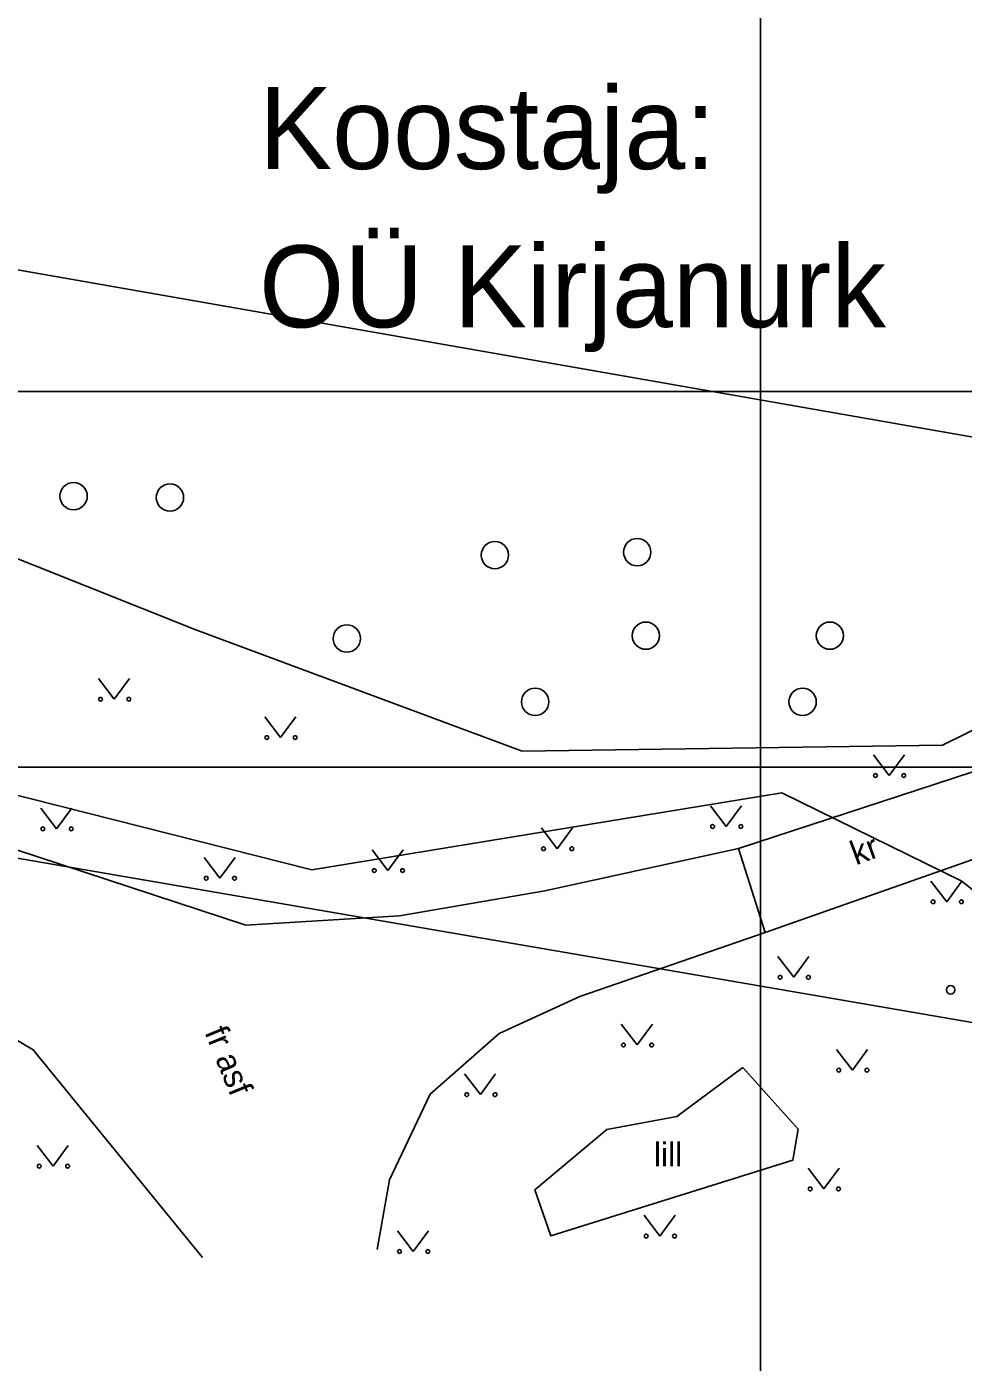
# Model space of a CAD drawing. Extents: x 554947 to 555436, y 6564938 to 6565792.
# Drawn here: x 555195.59 to 555223.03, y 6565130.48 to 6565169.6 of the extents above; entities that cross this region are included whole.
import ezdxf

# ---------------------------------------------------------------- set-up
doc = ezdxf.new("R2010")
doc.units = 0
for name, color, linetype in [('HALJASTUS', 7, 'Continuous'), ('KPOHULIIN', 7, 'Continuous'), ('PIIR', 7, 'Continuous'), ('PR_SIDE', 7, 'Continuous'), ('PUU', 7, 'Continuous'), ('TEE', 7, 'Continuous'), ('VORMISTUS', 7, 'Continuous'), ('VORMISTUS_1', 7, 'Continuous')]:
    doc.layers.add(name, color=color, linetype=linetype)

msp = doc.modelspace()

# ---------------------------------------------------------------- linework, layer by layer
at = {"layer": 'HALJASTUS'}
for p, q in [((555197.689, 6565150.508), (555198.153, 6565149.901)), ((555198.153, 6565149.901), (555198.598, 6565150.508)), ((555202.562, 6565149.385), (555203.025, 6565148.778)), ((555203.025, 6565148.778), (555203.471, 6565149.385)), ((555220.397, 6565148.274), (555220.861, 6565147.667)), ((555220.861, 6565147.667), (555221.306, 6565148.274)), ((555196, 6565146.709), (555196.464, 6565146.102)), ((555196.464, 6565146.102), (555196.909, 6565146.709)), ((555215.626, 6565146.78), (555216.089, 6565146.173)), ((555216.089, 6565146.173), (555216.535, 6565146.78)), ((555210.669, 6565146.129), (555211.133, 6565145.522)), ((555211.133, 6565145.522), (555211.578, 6565146.129)), ((555205.711, 6565145.488), (555206.174, 6565144.881)), ((555206.174, 6565144.881), (555206.62, 6565145.488)), ((555200.786, 6565145.261), (555201.25, 6565144.654)), ((555201.25, 6565144.654), (555201.695, 6565145.261)), ((555222.085, 6565144.574), (555222.548, 6565143.967)), ((555222.548, 6565143.967), (555222.994, 6565144.574)), ((555217.602, 6565142.361), (555218.065, 6565141.754)), ((555218.065, 6565141.754), (555218.511, 6565142.361)), ((555213.012, 6565140.378), (555213.475, 6565139.771)), ((555213.475, 6565139.771), (555213.921, 6565140.378)), ((555219.32, 6565139.641), (555219.783, 6565139.034)), ((555219.783, 6565139.034), (555220.229, 6565139.641)), ((555208.419, 6565138.924), (555208.883, 6565138.317)), ((555208.883, 6565138.317), (555209.328, 6565138.924)), ((555195.895, 6565136.829), (555196.358, 6565136.222)), ((555196.358, 6565136.222), (555196.804, 6565136.829)), ((555218.486, 6565136.16), (555218.949, 6565135.553)), ((555218.949, 6565135.553), (555219.395, 6565136.16)), ((555213.68, 6565134.781), (555214.143, 6565134.175)), ((555214.143, 6565134.175), (555214.589, 6565134.781)), ((555206.451, 6565134.328), (555206.914, 6565133.721)), ((555206.914, 6565133.721), (555207.36, 6565134.328))]:
    msp.add_line(p, q, dxfattribs=at)
for points in [[(555170.849, 6565163.433), (555170.802, 6565162.422), (555180.588, 6565157.338), (555194.166, 6565154.476), (555200.547, 6565151.934), (555210.105, 6565148.383), (555222.421, 6565148.556), (555228.239, 6565151.421), (555231.104, 6565153.786)], [(555216.57, 6565139.116), (555214.639, 6565137.676), (555212.583, 6565137.299), (555210.474, 6565135.526), (555210.946, 6565134.177), (555218.038, 6565136.397), (555218.195, 6565137.306), (555216.57, 6565139.116)]]:
    msp.add_lwpolyline(points, dxfattribs=at)
for centre, radius in [((555196.963, 6565155.852), 0.4), ((555199.786, 6565155.81), 0.4), ((555209.308, 6565154.124), 0.4), ((555213.479, 6565154.208), 0.4), ((555213.732, 6565151.763), 0.4), ((555219.125, 6565151.763), 0.4), ((555204.968, 6565151.678), 0.4), ((555210.488, 6565149.823), 0.4), ((555218.325, 6565149.823), 0.4), ((555197.752, 6565149.901), 0.055), ((555198.581, 6565149.901), 0.055), ((555202.624, 6565148.778), 0.055), ((555203.453, 6565148.778), 0.055), ((555220.46, 6565147.667), 0.055), ((555221.289, 6565147.667), 0.055), ((555215.688, 6565146.173), 0.055), ((555216.517, 6565146.173), 0.055), ((555196.063, 6565146.102), 0.055), ((555196.892, 6565146.102), 0.055), ((555210.732, 6565145.522), 0.055), ((555211.56, 6565145.522), 0.055), ((555200.848, 6565144.654), 0.055), ((555201.677, 6565144.654), 0.055), ((555205.773, 6565144.881), 0.055), ((555206.602, 6565144.881), 0.055), ((555222.147, 6565143.967), 0.055), ((555222.976, 6565143.967), 0.055), ((555217.664, 6565141.754), 0.055), ((555218.493, 6565141.754), 0.055), ((555213.074, 6565139.771), 0.055), ((555213.903, 6565139.771), 0.055), ((555219.382, 6565139.034), 0.055), ((555220.211, 6565139.034), 0.055), ((555208.482, 6565138.317), 0.055), ((555209.311, 6565138.317), 0.055), ((555195.957, 6565136.222), 0.055), ((555196.786, 6565136.222), 0.055), ((555218.548, 6565135.553), 0.055), ((555219.377, 6565135.553), 0.055), ((555213.742, 6565134.175), 0.055), ((555214.571, 6565134.175), 0.055), ((555206.513, 6565133.721), 0.055), ((555207.342, 6565133.721), 0.055)]:
    msp.add_circle(centre, radius, dxfattribs=at)
at = {"layer": 'KPOHULIIN'}
msp.add_lwpolyline([(555148.701, 6565153.258), (555226.644, 6565139.855), (555319.309, 6565121.586)], dxfattribs=at)
at = {"layer": 'PIIR'}
for points in [[(555293.54, 6565286.23), (555256.63, 6565245.54), (555254.61, 6565228.5), (555255.75, 6565226.79), (555261.42, 6565218.27), (555289.11, 6565186.6), (555315.28, 6565149.09), (555315.73, 6565134.86), (555310.07, 6565124.47), (555303.59, 6565115.89), (555291.54, 6565100.48), (555288.85, 6565092.31), (555275.41, 6565088.83), (555273.15, 6565087.34), (555239.11, 6565139), (555231.12, 6565150.64), (555225.89, 6565157.13), (555173.21, 6565166.35), (555173.84, 6565168.77), (555191.64, 6565237.48), (555195.28, 6565271.63)], [(555272.013, 6565013.369), (555140.74, 6565041.04), (555172.58, 6565163.93), (555173.21, 6565166.35), (555225.89, 6565157.13), (555231.12, 6565150.64), (555239.11, 6565139), (555273.15, 6565087.34), (555275.41, 6565088.83), (555288.85, 6565092.31), (555289.83, 6565088.53), (555290.166, 6565088.221)]]:
    msp.add_lwpolyline(points, dxfattribs=at)
at = {"layer": 'PR_SIDE'}
msp.add_lwpolyline([(555296.809, 6565115.615), (555286.607, 6565117.391), (555285.808, 6565118.252), (555287.837, 6565125.956), (555287.097, 6565126.919), (555245.342, 6565135.118), (555231.314, 6565137.915), (555222.994, 6565144.574), (555217.72, 6565147.16), (555203.944, 6565144.9), (555175.818, 6565152.015), (555157.882, 6565156.552), (555156.917, 6565156.236), (555156.093, 6565155.105)], dxfattribs=at)
at = {"layer": 'PUU'}
msp.add_circle((555222.663, 6565141.385), 0.125, dxfattribs=at)
at = {"layer": 'TEE'}
for points in [[(555205.86, 6565133.779), (555206.217, 6565135.824), (555207.407, 6565138.329), (555209.429, 6565140.104), (555211.794, 6565141.192), (555217.229, 6565143.067), (555216.442, 6565145.526), (555210.771, 6565144.283), (555206.511, 6565143.557), (555202.006, 6565143.277), (555191.831, 6565146.626), (555179.65, 6565150.043), (555174.155, 6565151.803), (555172.54, 6565153.141), (555170.207, 6565157.377), (555168.463, 6565160.669), (555168.3, 6565162.209)], [(555216.442, 6565145.526), (555223.819, 6565147.942), (555228.422, 6565150.319), (555233.413, 6565153.879)], [(555217.229, 6565143.067), (555224.725, 6565145.706), (555229.126, 6565147.942), (555234.467, 6565152.147)], [(555163.2, 6565141.618), (555168.594, 6565144.246), (555172.571, 6565146.598), (555178.227, 6565145.611), (555191.847, 6565141.953), (555195.778, 6565139.63), (555200.739, 6565133.541)]]:
    msp.add_lwpolyline(points, dxfattribs=at)
at = {"layer": 'VORMISTUS'}
msp.add_lwpolyline([(555217.086, 6564974.913), (555052.086, 6564974.913), (555052.086, 6565184.913), (555217.086, 6565184.913)], close=True, dxfattribs=at)
at = {"layer": 'VORMISTUS_1'}
for points in [[(555035.188, 6565444.913), (555245.188, 6565444.913), (555245.188, 6565147.913), (555035.188, 6565147.913)], [(555045.188, 6565158.913), (555235.188, 6565158.913), (555235.188, 6565433.913), (555045.188, 6565433.913)], [(555045.188, 6565433.913), (555235.188, 6565433.913), (555235.188, 6565158.913), (555045.188, 6565158.913)]]:
    msp.add_lwpolyline(points, close=True, dxfattribs=at)

# ---------------------------------------------------------------- texts
at = {"layer": 'HALJASTUS'}
msp.add_text('lill', height=0.7, dxfattribs=at).set_placement((555213.967, 6565136.212))
at = {"layer": 'TEE'}
for s, rotation, p in [('kr', 20.4711, (555219.887, 6565145.031)), ('fr asf', 292.2646, (555200.789, 6565140.147))]:
    msp.add_text(s, height=0.7, rotation=rotation, dxfattribs=at).set_placement(p)
at = {"layer": 'VORMISTUS_1'}
for s, p in [('Koostaja:', (555202.397, 6565165.434)), ('OÜ Kirjanurk', (555202.397, 6565160.796))]:
    msp.add_text(s, height=2.4, rotation=360, dxfattribs=at).set_placement(p)

doc.saveas('drawing.dxf')
